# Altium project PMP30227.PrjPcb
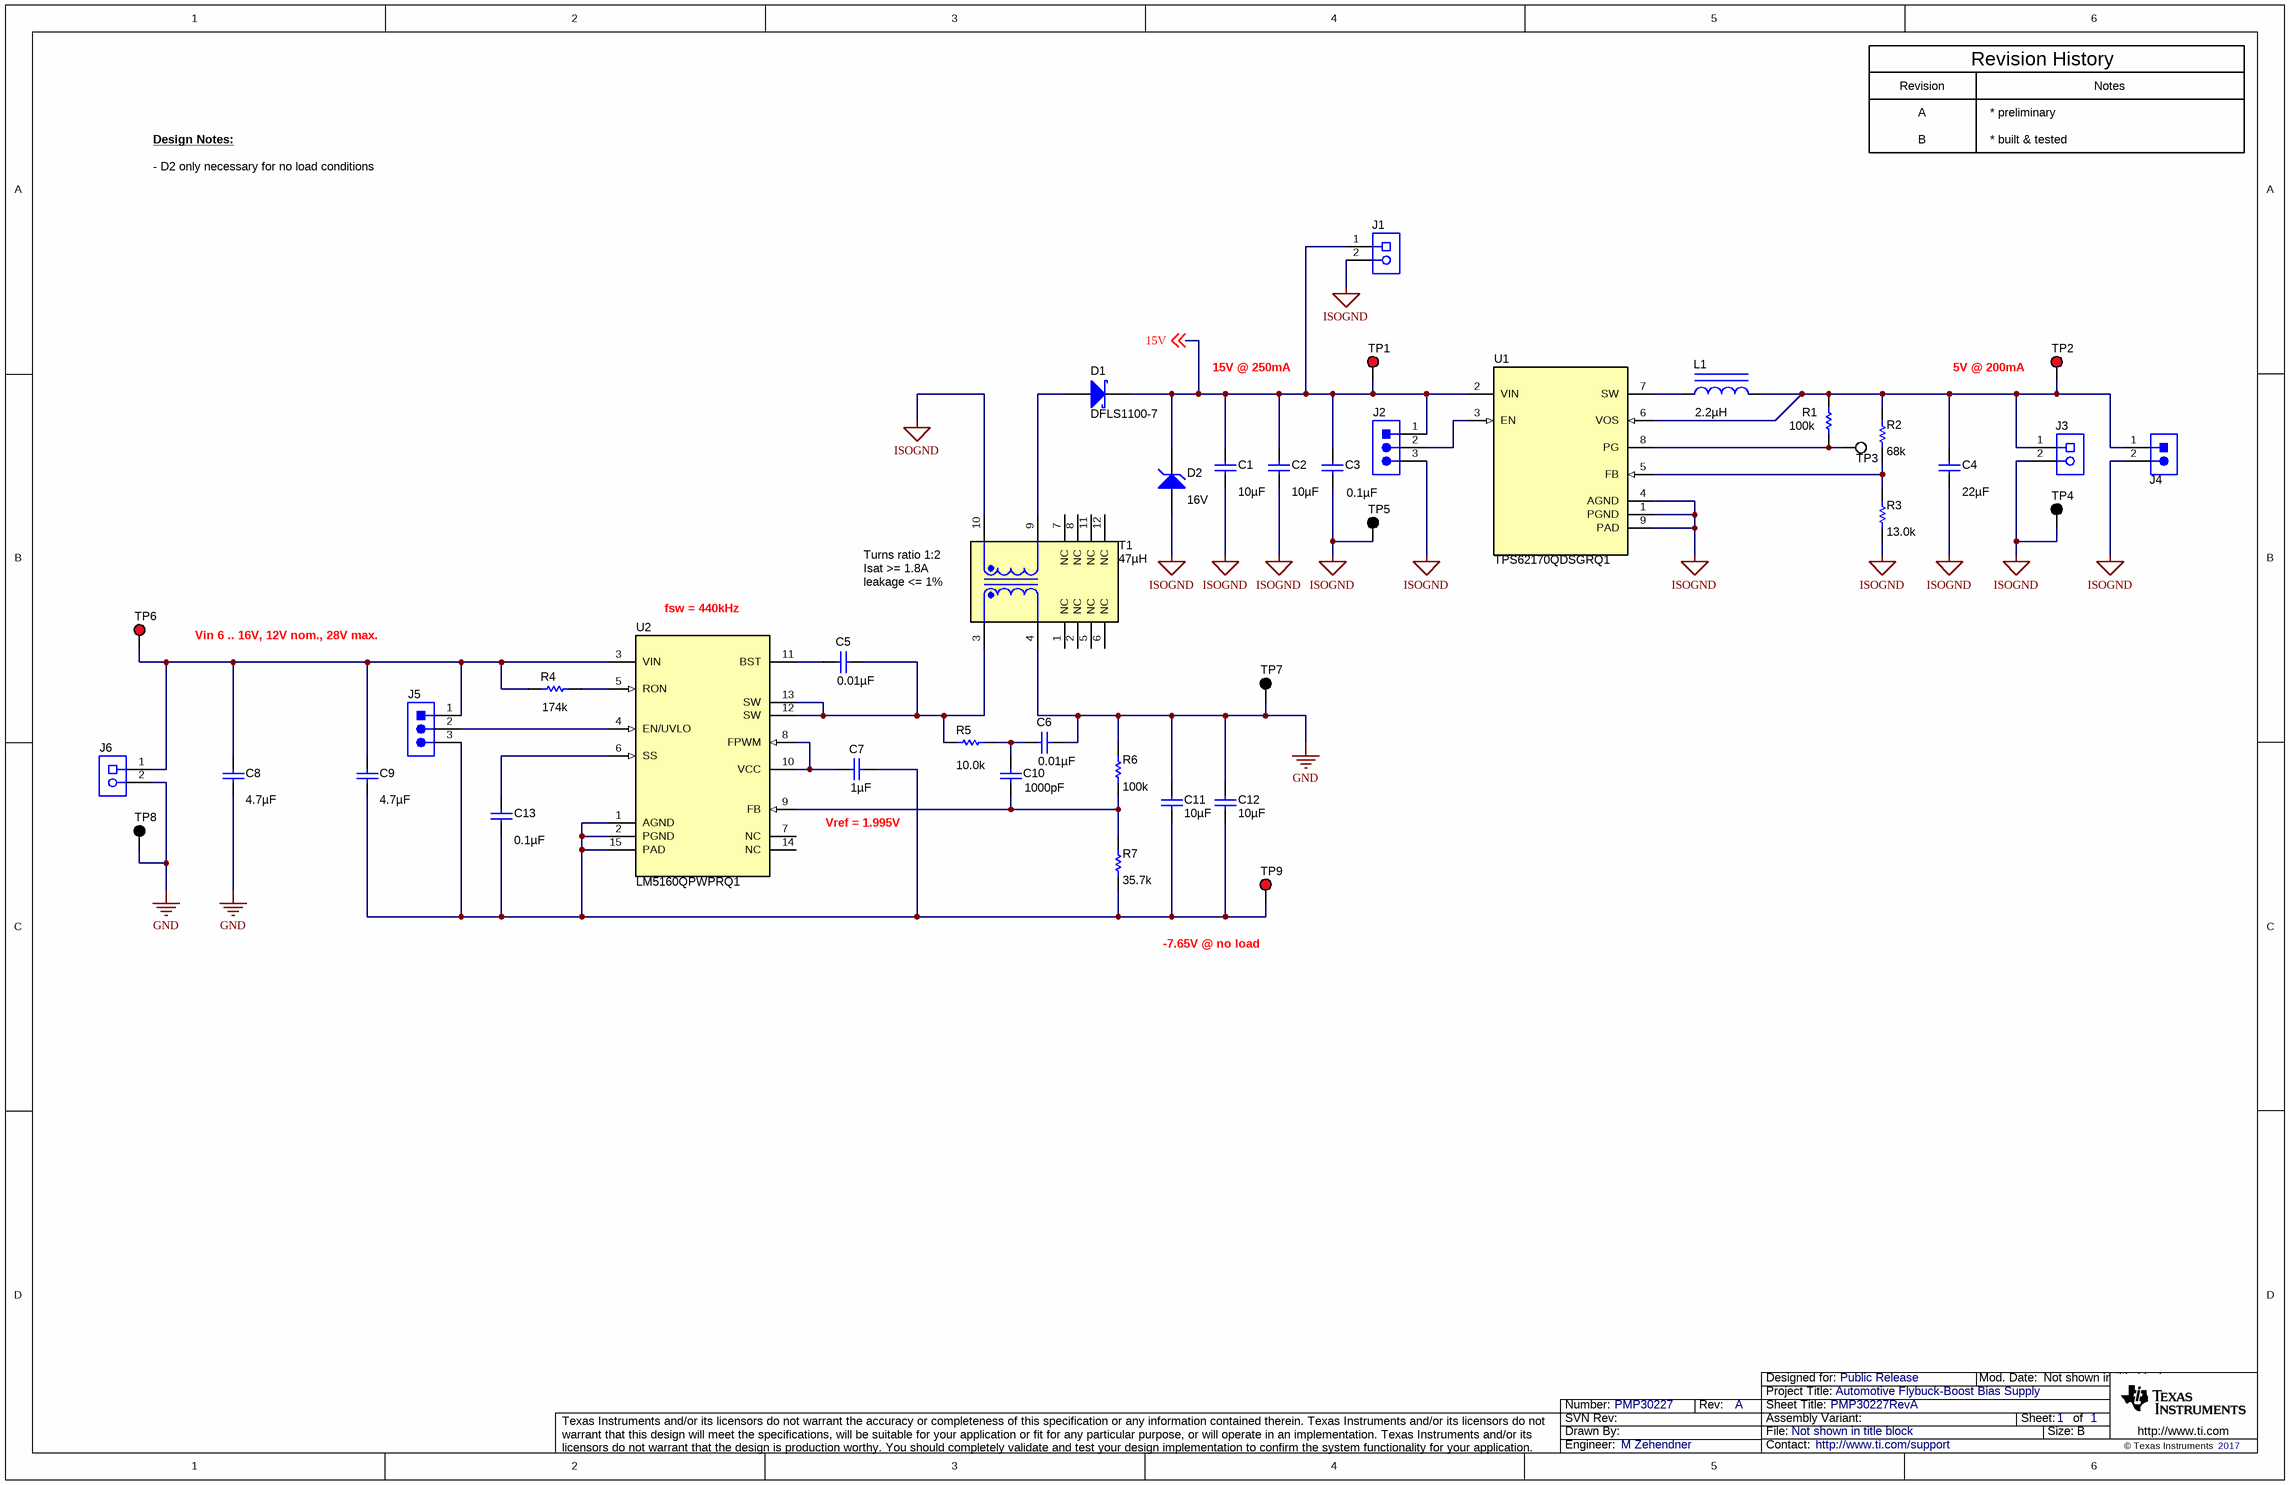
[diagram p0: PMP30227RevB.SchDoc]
CopyrightYear: 2017; EVM_Orderable: N/A; PCB_Rev: A; PRJ_Customer: Public Release; PRJ_Engineer: M Zehendner; PRJ_Number: PMP30227; PRJ_Title: Automotive Flybuck-Boost Bias Supply; SCH_Rev: A; TechSupport: http://www.ti.com/support; TID: ChangeMe!
1 sheet, 41 parts. Net scope: global (net labels, ports and power ports of the same name join across sheets).
Board file: PMP30227.PcbDoc

## Sheet PMP30227RevB.SchDoc: PMP30227RevA
size 431 x 279 mm; Date: Not shown in title block; ApprovedBy: Not shown in title block; CheckedBy: Not shown in title block; Author: Not shown in title block; CompanyName: Not shown in title block; Engineer: B. Geck; Organization: Not shown in title block; Address1: Not shown in title block; Address2: Not shown in title block; Address3: Not shown in title block; Address4: Not shown in title block; DocumentNumber: 1; Revision: Use project parameter SCH_Rev; SheetNumber: 1; SheetTotal: 1; PageSetup: Record=PageOptions¦CenterHorizontal=True¦CenterVertical=True¦PrintScale=0.62¦XCorrection=1.00¦YCorrection=1.00¦PrintKind=0¦BorderSize=5000000¦LeftOffset=0¦BottomOffset=0¦Orientation=2¦PaperLength=1000¦PaperWidth=1000¦Scale=100¦PaperSource=15¦PrintQuality=600¦MediaType=1¦DitherType=10¦PrintScaleMode=1¦PaperKind=Letter

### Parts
C1  ValueDisplayed: 10µF  [1210_220]  (hidden comment: GRM32DR71E106KA12L)
C2  ValueDisplayed: 10µF  [1210_220]  (hidden comment: GRM32DR71E106KA12L)
C3  ValueDisplayed: 0.1µF  [0603]  (hidden comment: GRM188R71E104KA01D)
C4  ValueDisplayed: 22µF  [1210_270]  (hidden comment: GRM32ER71A226ME20L)
C5  ValueDisplayed: 0.01µF  [0603]  (hidden comment: GRM188R71C103KA01D)
C6  ValueDisplayed: 0.01µF  [0603]  (hidden comment: GRM188R71H103KA01D)
C7  ValueDisplayed: 1µF  [0603]  (hidden comment: GRM188R71C105KA12D)
C8  ValueDisplayed: 4.7µF  [1210_270]  (hidden comment: GRM32ER71H475KA88L)
C9  ValueDisplayed: 4.7µF  [1210_270]  (hidden comment: GRM32ER71H475KA88L)
C10  ValueDisplayed: 1000pF  [0603]  (hidden comment: GRM188R72A102KA01D)
C11  ValueDisplayed: 10µF  [1210_220]  (hidden comment: GRM32DR71E106KA12L)
C12  ValueDisplayed: 10µF  [1210_220]  (hidden comment: GRM32DR71E106KA12L)
C13  ValueDisplayed: 0.1µF  [0603]  (hidden comment: GRM188R71C104KA01D)
D1  DFLS1100-7  [PowerDI123]
D2  value 16V  [SOD-123]  (hidden comment: MMSZ5246B-7-F)
J1  691 101 710 002  [Wurth_691101710002]  (value not drawn)
J2  800-10-003-10-001000  [Mill-Max_800-10-003-10-001000]  (value not drawn)
J3  691 101 710 002  [Wurth_691101710002]  (value not drawn)
J4  800-10-002-10-001000  [Mill-Max_800-10-002-10-001000]  (value not drawn)
J5  800-10-003-10-001000  [Mill-Max_800-10-003-10-001000]  (value not drawn)
J6  691 101 710 002  [Wurth_691101710002]  (value not drawn)
L1  ValueDisplayed: 2.2µH  [XPL2010]  (hidden comment: XPL2010-222MLB)
R1  ValueDisplayed: 100k  [0603]  (hidden comment: CRCW0603100KFKEA)
R2  ValueDisplayed: 68k  [0603]  (hidden comment: CRCW060368K0JNEA)
R3  ValueDisplayed: 13.0k  [0603]  (hidden comment: CRCW060313K0FKEA)
R4  ValueDisplayed: 174k  [0603]  (hidden comment: CRCW0603174KFKEA)
R5  ValueDisplayed: 10.0k  [0603]  (hidden comment: CRCW060310K0FKEA)
R6  ValueDisplayed: 100k  [0603]  (hidden comment: CRCW0603100KFKEA)
R7  ValueDisplayed: 35.7k  [0603]  (hidden comment: CRCW060335K7FKEA)
T1  ValueDisplayed: 47µH  [Coilcraft_WA8417-AL]  (hidden comment: WA8417-AL)
TP1  5010  [Keystone5010]  (value not drawn)
TP2  5010  [Keystone5010]  (value not drawn)
TP3  5012  [Keystone5012]  (value not drawn)
TP4  5011  [Keystone5011]  (value not drawn)
TP5  5011  [Keystone5011]  (value not drawn)
TP6  5010  [Keystone5010]  (value not drawn)
TP7  5011  [Keystone5011]  (value not drawn)
TP8  5011  [Keystone5011]  (value not drawn)
TP9  5010  [Keystone5010]  (value not drawn)
U1  TPS62170QDSGRQ1  [DSG0008A]
U2  LM5160QPWPRQ1  [PWP0014A_N]

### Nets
GND: C6.1 C8.2 C11.1 C12.1 J6.2 R6.2 T1.4 TP7.1 TP8.1
ISOGND: C1.2 C2.2 C3.2 C4.2 D2.2(A) J1.2 J2.3 J3.2 J4.2 R3.1 T1.10 TP4.1 TP5.1 U1.1(PGND) U1.4(AGND) U1.9(PAD)
15V: C1.1 C2.1 C3.1 D1.1(K) D2.1(K) J1.1 J2.1 TP1.1 U1.2(VIN) ; off-sheet 15V
NetC4_1: C4.1 J3.1 J4.1 L1.2 R1.2 R2.2 TP2.1 U1.6(VOS)
NetC5_1: C5.1 R5.1 T1.3 U2.12(SW) U2.13(SW)
NetC5_2: C5.2 U2.11(BST)
NetC6_2: C6.2 C10.1 R5.2
NetC7_1: C7.1 C9.2 C11.2 C12.2 C13.2 J5.3 R7.1 TP9.1 U2.1(AGND) U2.2(PGND) U2.15(PAD)
NetC7_2: C7.2 U2.8(FPWM) U2.10(VCC)
NetC8_1: C8.1 C9.1 J5.1 J6.1 R4.1 TP6.1 U2.3(VIN)
NetC10_2: C10.2 R6.1 R7.2 U2.9(FB)
NetC13_1: C13.1 U2.6(SS)
NetD1_2: D1.2(A) T1.9
NetJ2_2: J2.2 U1.3(EN)
NetJ5_2: J5.2 U2.4(EN/UVLO)
NetL1_1: L1.1 U1.7(SW)
NetR1_1: R1.1 TP3.1 U1.8(PG)
NetR2_1: R2.1 R3.2 U1.5(FB)
NetR4_2: R4.2 U2.5(RON)

Not connected (* = marked no-connect by the designer): T1 1(NC) 2(NC) 5(NC) 6(NC) 7(NC) 8(NC) 11(NC) 12(NC); U2 7(NC) 14(NC)

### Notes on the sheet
- Revision
- Revision History
- Notes
- Design Notes:
- - D2 only necessary for no load conditions
- A
- B
- * preliminary
- * built & tested
- 15V @ 250mA
- (near TP2) 5V @ 200mA
- (near T1) Turns ratio 1:2
- (near T1) Isat >= 1.8A
- (near TP6) Vin 6 .. 16V, 12V nom., 28V max.
- (near U2) fsw = 440kHz
- (near T1) leakage <= 1%
- Vref = 1.995V
- (near TP9) -7.65V @ no load

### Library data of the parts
C1 C2 C11 C12 = GRM32DR71E106KA12L: CAP, CERM, 10 µF, 25 V, +/- 10%, X7R, 1210; Manufacturer: MuRata; Polarized: N; CompType: Capacitor; Value: 10uF; U/M: EA; Cap_F: 0.00001; Tolerance_%: 10; Value1: Unknown; VDC_V: 25; Value2: 25V; TaMin_C: -55; TaMax_C: 125; Cap_Case: 1210; SizeArea_mm2: 8; SizeAreaWB_mm2: 14.7; SizeX_mm: 3.2; SizeY_mm: 2.5; SizeZ_mm: 2.2; AEC Category: Q200
C3 = GRM188R71E104KA01D: CAP, CERM, 0.1 µF, 25 V, +/- 10%, X7R, 0603; Manufacturer: MuRata; Polarized: N; CompType: Capacitor; Value: 0.1uF; U/M: EA; Cap_F: 0.0000001; Tolerance_%: 10; Value1: Unknown; VDC_V: 25; Value2: 25V; TaMin_C: -55; TaMax_C: 125; SizeArea_mm2: 1.28; SizeAreaWB_mm2: 4.68; SizeX_mm: 1.6; SizeY_mm: 0.8; SizeZ_mm: 1; AEC Category: Q200
C4 = GRM32ER71A226ME20L: CAP, CERM, 22 µF, 10 V, +/- 10%, X7R, 1210; Manufacturer: MuRata; Polarized: N; CompType: Capacitor; Value: 22uF; U/M: EA; Cap_F: 0.000022; Tolerance_%: 10; ESR_ohm: 0.002; Value1: 0.002 ohm; Value2: 10V; IRMS_A: 3.2; TaMin_C: -55; TaMax_C: 125; Cap_Case: 1210; SizeArea_mm2: 8; SizeAreaWB_mm2: 14.7; SizeY_mm: 2.5; SizeZ_mm: 2.7; AEC Category: Q200
C5 = GRM188R71C103KA01D: CAP, CERM, 0.01 µF, 16 V, +/- 10%, X7R, 0603; Manufacturer: MuRata; Polarized: N; CompType: Capacitor; Value: 0.01uF; U/M: EA; Cap_F: 0.00000001; Tolerance_%: 10; Value1: Unknown; VDC_V: 16; Value2: 16V; TaMin_C: -55; TaMax_C: 125; SizeArea_mm2: 1.28; SizeAreaWB_mm2: 4.68; SizeX_mm: 1.6; SizeY_mm: 0.8; SizeZ_mm: 1; AEC Category: Q200
C6 = GRM188R71H103KA01D: CAP, CERM, 0.01 µF, 50 V, +/- 10%, X7R, 0603; Manufacturer: MuRata; Polarized: N; CompType: Capacitor; Value: 0.01uF; U/M: EA; Cap_F: 0.00000001; Tolerance_%: 10; Value1: Unknown; VDC_V: 50; Value2: 50V; TaMin_C: -55; TaMax_C: 125; SizeArea_mm2: 1.28; SizeAreaWB_mm2: 4.68; SizeX_mm: 1.6; SizeY_mm: 0.8; SizeZ_mm: 1; AEC Category: Q200
C7 = GRM188R71C105KA12D: CAP, CERM, 1 µF, 16 V, +/- 10%, X7R, 0603; Manufacturer: MuRata; Polarized: N; CompType: Capacitor; Value: 1uF; U/M: EA; Cap_F: 0.000001; Tolerance_%: 10; ESR_ohm: 0.011; Value1: 0.011 ohm; VDC_V: 16; Value2: 16V; TaMin_C: -55; TaMax_C: 125; SizeArea_mm2: 1.28; SizeAreaWB_mm2: 4.68; SizeX_mm: 1.6; SizeY_mm: 0.8; SizeZ_mm: 1; AEC Category: Q200
C8 C9 = GRM32ER71H475KA88L: CAP, CERM, 4.7 µF, 50 V, +/- 10%, X7R, 1210; Manufacturer: MuRata; Polarized: N; CompType: Capacitor; Value: 4.7uF; U/M: EA; Cap_F: 0.0000047; Tolerance_%: 10; ESR_ohm: 0.002; Value1: 0.002 ohm; VDC_V: 50; Value2: 50V; TaMin_C: -55; TaMax_C: 125; Cap_Case: 1210; SizeArea_mm2: 8; SizeAreaWB_mm2: 14.7; SizeX_mm: 3.2; SizeY_mm: 2.5; SizeZ_mm: 2.7; AEC Category: Q200
C10 = GRM188R72A102KA01D: CAP, CERM, 1000 pF, 100 V, +/- 10%, X7R, 0603; Manufacturer: MuRata; Polarized: N; CompType: Capacitor; Value: 1000pF; U/M: EA; Cap_F: 0.000000001; Tolerance_%: 10; Value1: Unknown; VDC_V: 100; Value2: 100V; TaMin_C: -55; TaMax_C: 125; SizeArea_mm2: 1.28; SizeAreaWB_mm2: 4.68; SizeX_mm: 1.6; SizeY_mm: 0.8; SizeZ_mm: 1; AEC Category: Q200
C13 = GRM188R71C104KA01D: CAP, CERM, 0.1 µF, 16 V, +/- 10%, X7R, 0603; Manufacturer: MuRata; Polarized: N; CompType: Capacitor; Value: 0.1uF; U/M: EA; Cap_F: 0.0000001; Tolerance_%: 10; Value1: Unknown; VDC_V: 16; Value2: 16V; TaMin_C: -55; TaMax_C: 125; SizeArea_mm2: 1.28; SizeAreaWB_mm2: 4.68; SizeX_mm: 1.6; SizeY_mm: 0.8; SizeZ_mm: 1; AEC Category: Q200
D1 = DFLS1100-7: Diode, Schottky, 100 V, 1 A, PowerDI123; Manufacturer: Diodes Inc.; U/M: EA; Vf_V: 0.77; Value: 100V; Value1: 1A; Value2: 0.77V; Io_A: 1; Vr_V: 100; TJmax_C: 175; RJC_CperW: 7; SizeAreaWB_mm2: 13.066; SizeArea_mm2: 6.586; SizeX_mm: 3.7; SizeY_mm: 1.78; SizeZ_mm: 0.98; AEC Category: Q101
D2 = MMSZ5246B-7-F: Diode, Zener, 16 V, 500 mW, SOD-123; Manufacturer: Diodes Inc.; SymbolCreator: a0412235; U/M: EA; Power_W: 0.5; Vz_V: 16; Value1: 0.5W; RJA_CperW: 350; SizeAreaWB_mm2: 13.095; SizeArea_mm2: 6.545; SizeX_mm: 3.85; SizeY_mm: 1.7; SizeZ_mm: 1.35; AEC Category: Q101
J1 J3 J6 = 691 101 710 002: Terminal Block, 5 mm, 2x1, Tin, TH; Manufacturer: Wurth Elektronik; SymbolCreator: a0412235
J2 J5 = 800-10-003-10-001000: Header, 100mil, 3x1, TH; Manufacturer: Mill-Max; SymbolCreator: a0799628
J4 = 800-10-002-10-001000: Header, 100mil, 2x1, TH; Manufacturer: Mill-Max; SymbolCreator: a0412235
L1 = XPL2010-222MLB: Inductor, Shielded, Composite, 2.2 µH, 1.3 A, 0.16 ohm, SMD; Manufacturer: Coilcraft; Value: 2.2uH; Ind_H: 2.2E-6; Imax_A: 1.3; Irms: 1.3A @ 40C rise; Isat: 1.35A @ 30% inductance drop; DCR_ohm: 0.16; Value2: 1.3A; SizeAreaWB_mm2: 8.7; SizeArea_mm2: 3.8; SizeX_mm: 2; SizeY_mm: 1.9; SizeZ_mm: 1; AEC Category: Q200
R1 R6 = CRCW0603100KFKEA: RES, 100 k, 1%, 0.1 W, 0603; Manufacturer: Vishay-Dale; CompType: Resistor; Value: 100k; Res_ohm: 100000; Tolerance_%: 1; Power_W: 0.1; Value2: 0.1W; VDC_V: 75; TempCo: 100 ppm/C; SizeArea_mm2: 1.28; SizeX_mm: 1.6; SizeY_mm: 0.8; EIA_Code: E96; U/M: EA; AEC Category: Q200
R2 = CRCW060368K0JNEA: RES, 68 k, 5%, 0.1 W, 0603; Manufacturer: Vishay-Dale; CompType: Resistor; Value: 68k; Res_ohm: 68000; Value_Code: 68k0; Tolerance_%: 5; Power_W: 0.1; Value2: 0.1W; VDC_V: 75; TempCo: 200 ppm/C; SizeArea_mm2: 1.28; SizeX_mm: 1.6; SizeY_mm: 0.8; SizeZ_mm: 1; EIA_Code: E24; U/M: EA; AEC Category: Q200
R3 = CRCW060313K0FKEA: RES, 13.0 k, 1%, 0.1 W, 0603; Manufacturer: Vishay-Dale; CompType: Resistor; Value: 13.0k; Res_ohm: 13000; Value_Code: 13k0; Tolerance_%: 1; Power_W: 0.1; Value2: 0.1W; VDC_V: 75; TempCo: 100 ppm/C; SizeArea_mm2: 1.28; SizeX_mm: 1.6; SizeY_mm: 0.8; EIA_Code: E96; U/M: EA; AEC Category: Q200
R4 = CRCW0603174KFKEA: RES, 174 k, 1%, 0.1 W, 0603; Manufacturer: Vishay-Dale; CompType: Resistor; Value: 174k; Res_ohm: 174000; Tolerance_%: 1; Power_W: 0.1; Value2: 0.1W; VDC_V: 75; TempCo: 100 ppm/C; SizeArea_mm2: 1.28; SizeX_mm: 1.6; SizeY_mm: 0.8; EIA_Code: E96; U/M: EA; AEC Category: Q200
R5 = CRCW060310K0FKEA: RES, 10.0 k, 1%, 0.1 W, 0603; Manufacturer: Vishay-Dale; CompType: Resistor; Value: 10.0k; Res_ohm: 10000; Value_Code: 10k0; Tolerance_%: 1; Power_W: 0.1; Value2: 0.1W; VDC_V: 75; TempCo: 100 ppm/C; SizeArea_mm2: 1.28; SizeX_mm: 1.6; SizeY_mm: 0.8; EIA_Code: E96; U/M: EA; AEC Category: Q200
R7 = CRCW060335K7FKEA: RES, 35.7 k, 1%, 0.1 W, 0603; Manufacturer: Vishay-Dale; CompType: Resistor; Value: 35.7k; Res_ohm: 35700; Value_Code: 35k7; Tolerance_%: 1; Power_W: 0.1; Value2: 0.1W; VDC_V: 75; TempCo: 100 ppm/C; SizeArea_mm2: 1.28; SizeX_mm: 1.6; SizeY_mm: 0.8; EIA_Code: E96; U/M: EA; AEC Category: Q200
T1 = WA8417-AL: Transformer, 47 uH, SMT; Manufacturer: Coilcraft; SymbolCreator: Altium; Value: 47uH; Lp: 47; DCR_ohm: 0.145; LeakageL: 10.9; Ns1toNp: 2; Rs1: 0.3; SizeAreaWB_mm2: 460.8; SizeArea_mm2: 378.4; SizeX_mm: 22; SizeY_mm: 17.2; SizeZ_mm: 8.64
TP1 TP2 TP6 TP9 = 5010: Test Point, Multipurpose, Red, TH; Manufacturer: Keystone; CompType: Test Point Loop; ContactFinish: Silver
TP3 = 5012: Test Point, Multipurpose, White, TH; Manufacturer: Keystone; CompType: Test Point Loop; ContactFinish: Silver
TP4 TP5 TP7 TP8 = 5011: Test Point, Multipurpose, Black, TH; Manufacturer: Keystone; CompType: Test Point Loop; ContactFinish: Silver
U1 = TPS62170QDSGRQ1: 3-17V 0.5A Automotive Step-Down Converter in 2x2 QFN package, DSG0008A (WSON-8); Alternate PartNumber: TPS62170QDSGTQ1; Manufacturer: Texas Instruments; SymbolCreator: Altium; SizeArea_mm2: 4; SizeAreaWB_mm2: 9; SizeX_mm: 2; SizeZ_mm: 0.8; CompType: IC; U/M: EA
U2 = LM5160QPWPRQ1: Wide Input 65V, 1.5A Synchronous Buck / Fly-Buck(TM) Converter, PWP0014A (TSSOP-14); Alternate PartNumber: LM5160QPWPTQ1; Manufacturer: Texas Instruments; SymbolCreator: a0411947; SizeArea_mm2: 32; SizeAreaWB_mm2: 58.8; SizeX_mm: 6.4; SizeY_mm: 5; SizeZ_mm: 1.2; CompType: IC; U/M: EA

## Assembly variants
001: alternate parts D1 -> VS-30BQ100TRPBF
